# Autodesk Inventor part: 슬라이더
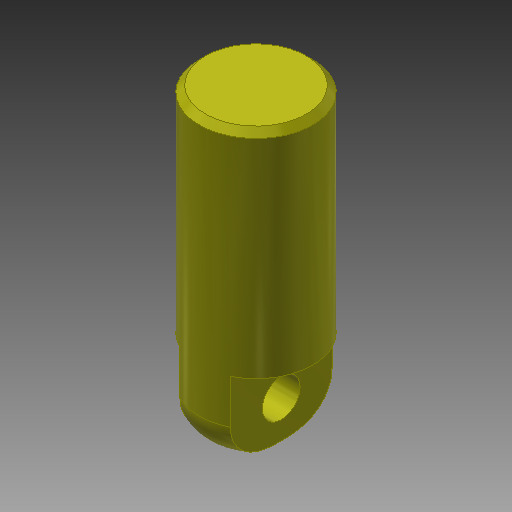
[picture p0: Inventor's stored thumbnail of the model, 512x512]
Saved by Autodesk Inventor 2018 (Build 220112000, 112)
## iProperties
Created: 2016-08
Part Number: 슬라이더
Material: 강철, 탄소
Document SubType Name: Modeling
Designer: mduedu
Density: 7.87 g/cm^3
Appearance: 노란색
Author: mduedu
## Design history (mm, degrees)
sketch "스케치1"
  geometry: C1 r 9 at (0, 0); 1 further point
  constraints: 1 centre point, 1 coincident
  dimensions: "d0" = 18 diameter of C1
extrude "돌출1" new body sketch "스케치1" distance "d1" = 47; taper "d2" = 0 deg
fillet "모깎기1" dims "d21" = 6
sketch "스케치6"
  geometry: L1 (9, 6)-(9, 47) reference; L2 (-9, 6)-(-9, 47) reference; L3 (9, 47)-(-9, 47) reference; L4 (0, 47)-(0, 0); L5 (9, 13)-(4, 13); L6 (4, 13)-(4, 0); L7 (4, 0)-(9, 0); L8 (9, 0)-(9, 13); L9 (-9, 13)-(-4, 13); L10 (-4, 13)-(-4, 0); L11 (-4, 0)-(-9, 0); L12 (-9, 0)-(-9, 13)
  constraints: 18 end point, 4 symmetric about line, 2 parallel, 2 perpendicular, 1 horizontal, 1 horizontal alignment, 1 midpoint, 1 point on line
  dimensions: "d22" = 13 distance of L7.end L5.start; "d24" = 4 distance between parallel lines of L6 L4
extrude "돌출5" cut sketch "스케치6" extent not by distance; stored distance "d25" = 8; taper "d26" = 0 deg
sketch "스케치8"
  geometry: C1 r 3 at (6, 0); 1 further point
  constraints: 1 centre point, 1 horizontal alignment
  dimensions: "d27" = 6 diameter of C1; "d28" = 6 distance of point (0, 0) C1.centre
extrude "돌출6" cut sketch "스케치8" extent not by distance; stored distance "d29" = 8; taper "d30" = 0 deg
chamfer "모따기2" distance "d43" = 1; stored, may be unused: second distance "d44" = 2, angle "d45" = 30 deg
node "솔리드1"
